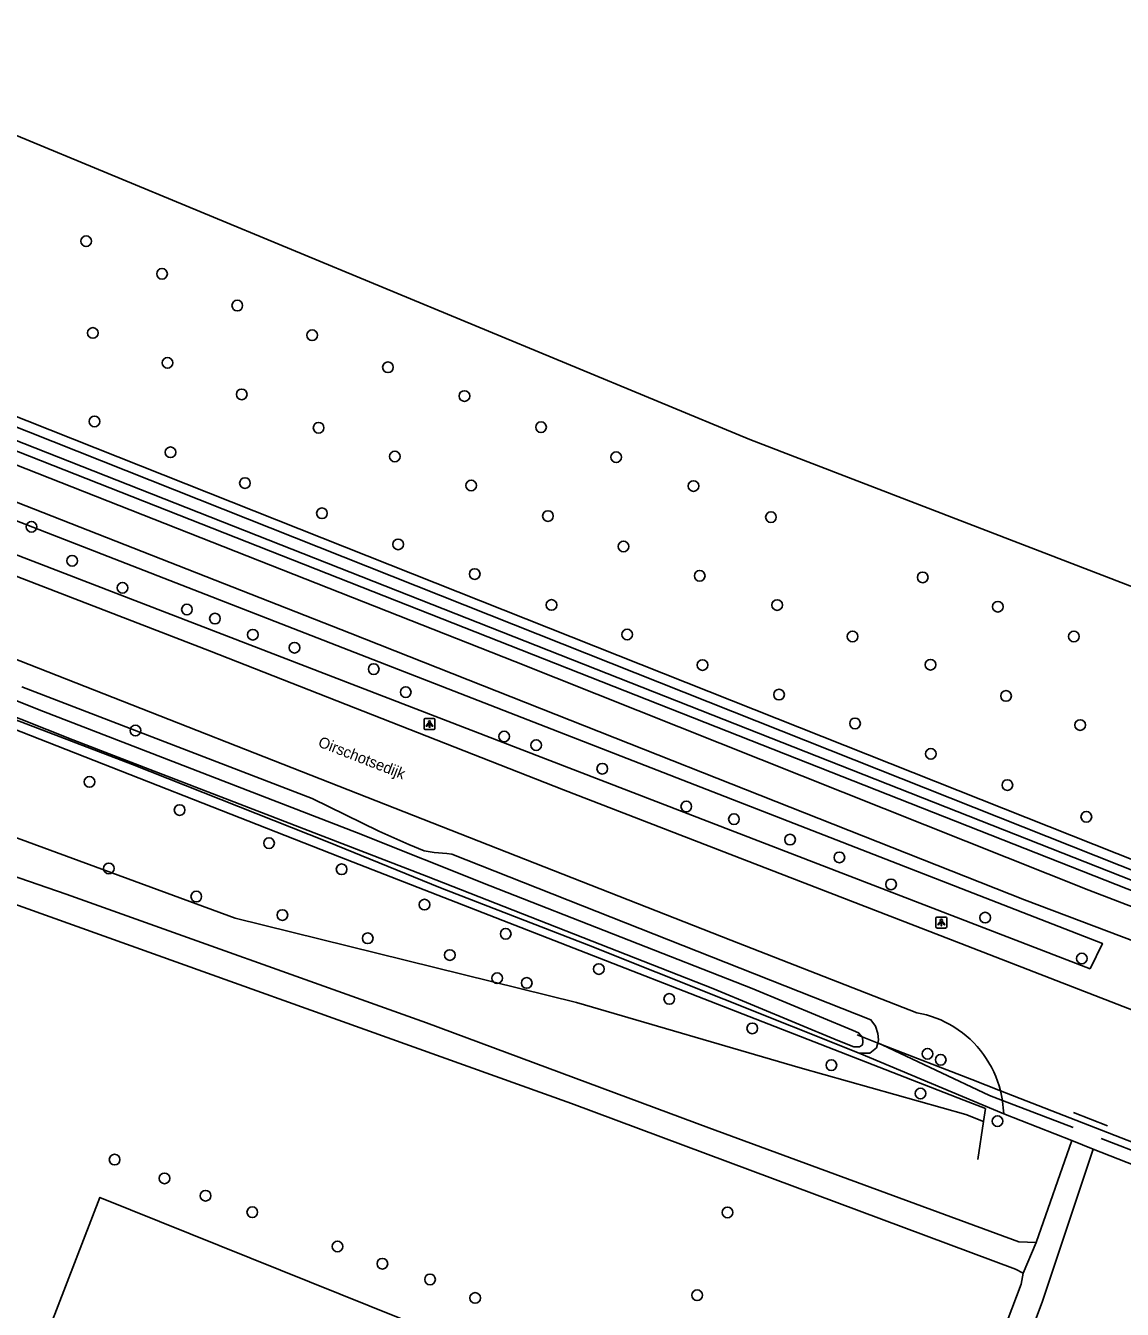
# Model space of a CAD drawing. Extents: x 155209 to 156823, y 385356 to 388482.
# Drawn here: x 155552.9 to 155653.4, y 386737.4 to 386855.1 of the extents above; entities that cross this region are included whole.
import ezdxf

# ---------------------------------------------------------------- set-up
doc = ezdxf.new("R2010")
doc.units = 0
for name, color, linetype in [('IMGEO_Berm_groen', 7, 'Continuous'), ('IMGEO_Boom', 7, 'Continuous'), ('IMGEO_Duiker', 7, 'Continuous'), ('IMGEO_Fietspad_gesloten', 7, 'Continuous'), ('IMGEO_Gemengd_bos', 7, 'Continuous'), ('IMGEO_Groenvoorziening', 7, 'Continuous'), ('IMGEO_Hek', 7, 'Continuous'), ('IMGEO_Lichtpunt', 7, 'Continuous'), ('IMGEO_Openbare_ruimte_label', 7, 'Continuous'), ('IMGEO_Rijbaan_lokaal_gesloten', 7, 'Continuous'), ('IMGEO_Rijbaan_lokaal_halfverhard', 7, 'Continuous'), ('IMGEO_Waterloop', 7, 'Continuous')]:
    doc.layers.add(name, color=color, linetype=linetype)

msp = doc.modelspace()

# ---------------------------------------------------------------- linework, layer by layer
at = {"layer": 'IMGEO_Berm_groen'}
for points in [[(155482.51, 386846.03), (155487.29, 386843.95), (155500, 386838.42), (155529.93, 386825.41), (155544.85, 386818.92), (155660.25, 386773.45)], [(155631.02, 386761.84), (155631.09, 386762.12), (155631.03, 386762.7), (155630.81, 386763.38), (155630.4, 386763.97), (155591.96, 386779.14), (155591.53, 386779.21), (155590.36, 386779.31), (155589.43, 386779.44), (155588.04, 386780.02), (155585.27, 386781.26), (155579.17, 386784.25), (155552.56, 386794.49)], [(155642.45, 386756.57), (155641.27, 386757.02), (155631.41, 386761.68), (155631.02, 386761.84)]]:
    msp.add_lwpolyline(points, dxfattribs=at)
at = {"layer": 'IMGEO_Boom'}
for centre in [(155558.45, 386835.33), (155565.41, 386832.34), (155572.31, 386829.43), (155559.07, 386826.92), (155579.17, 386826.71), (155565.91, 386824.18), (155586.12, 386823.77), (155572.71, 386821.29), (155593.13, 386821.14), (155559.22, 386818.81), (155579.76, 386818.23), (155600.15, 386818.28), (155566.19, 386815.98), (155586.75, 386815.6), (155607.04, 386815.53), (155573.01, 386813.16), (155593.75, 386812.94), (155614.13, 386812.89), (155580.07, 386810.39), (155600.79, 386810.14), (155621.23, 386810.04), (155553.44, 386809.15), (155587.05, 386807.54), (155607.71, 386807.35), (155557.17, 386806.04), (155594.07, 386804.82), (155614.7, 386804.66), (155635.14, 386804.52), (155561.78, 386803.56), (155567.69, 386801.57), (155601.11, 386801.99), (155621.8, 386801.98), (155642.03, 386801.83), (155570.26, 386800.74), (155573.73, 386799.26), (155608.05, 386799.28), (155628.71, 386799.1), (155649, 386799.1), (155577.55, 386798.07), (155584.81, 386796.11), (155614.95, 386796.48), (155635.85, 386796.51), (155587.75, 386794), (155621.97, 386793.77), (155642.78, 386793.65), (155628.94, 386791.13), (155649.58, 386790.98), (155562.97, 386790.48), (155596.77, 386789.93), (155599.71, 386789.14), (155635.89, 386788.34), (155605.77, 386786.98), (155558.76, 386785.77), (155642.9, 386785.48), (155567.02, 386783.19), (155613.47, 386783.52), (155650.14, 386782.57), (155617.84, 386782.36), (155575.22, 386780.16), (155622.98, 386780.48), (155560.53, 386777.84), (155581.87, 386777.76), (155627.5, 386778.85), (155632.24, 386776.38), (155568.55, 386775.26), (155589.47, 386774.52), (155576.44, 386773.57), (155640.87, 386773.33), (155596.91, 386771.85), (155584.26, 386771.44), (155591.79, 386769.9), (155649.73, 386769.58), (155605.45, 386768.62), (155596.13, 386767.78), (155598.84, 386767.34), (155611.91, 386765.88), (155619.52, 386763.18), (155635.58, 386760.85), (155636.79, 386760.3), (155626.77, 386759.81), (155634.94, 386757.21), (155642, 386754.68), (155561.06, 386751.15), (155565.64, 386749.43), (155569.4, 386747.84), (155573.68, 386746.33), (155617.25, 386746.31), (155581.49, 386743.19), (155585.61, 386741.61), (155589.98, 386740.17), (155594.11, 386738.47), (155614.46, 386738.72)]:
    msp.add_circle(centre, 0.489, dxfattribs=at)
at = {"layer": 'IMGEO_Duiker'}
msp.add_lwpolyline([(155666.33, 386748.06), (155664.02, 386748.99), (155661.42, 386750), (155656.8, 386751.8), (155642.28, 386757.45), (155639.65, 386758.48), (155631.41, 386761.68), (155629.14, 386762.58)], dxfattribs=at)
at = {"layer": 'IMGEO_Fietspad_gesloten'}
for points in [[(155664.94, 386770.25), (155650.37, 386775.84), (155597.75, 386796.8), (155542.24, 386818.67), (155529.41, 386824.07), (155500, 386836.47), (155486.55, 386842.14), (155476.96, 386846.12)], [(155657.25, 386770.12), (155644.46, 386774.96), (155582.64, 386799.4), (155542.08, 386815.32), (155528.28, 386821.17), (155500, 386833.17), (155494.87, 386835.35), (155485.35, 386839.2), (155476.04, 386842.96), (155472.84, 386844.21)]]:
    msp.add_lwpolyline(points, dxfattribs=at)
at = {"layer": 'IMGEO_Gemengd_bos'}
for points in [[(155501.63, 386865.96), (155619.3, 386817.16), (155711.43, 386781.69)], [(155484.42, 386847.58), (155500, 386841.03), (155546.79, 386821.35), (155661.24, 386775.91)], [(155609.34, 386713.39), (155610.76, 386716.71), (155614.71, 386725.57), (155559.71, 386747.69), (155554.38, 386733.89), (155557.42, 386732.74)]]:
    msp.add_lwpolyline(points, dxfattribs=at)
at = {"layer": 'IMGEO_Groenvoorziening'}
for points in [[(155463.65, 386822.31), (155477.84, 386817.46), (155484.11, 386815.5), (155520.82, 386802.04), (155551.64, 386790.69), (155581.69, 386778.9), (155638.9, 386756.61), (155640.89, 386755.83), (155640.71, 386754.64), (155639.1, 386755.3), (155623.92, 386759.56), (155603.41, 386765.55), (155572.12, 386773.29), (155551.59, 386780.84), (155540.07, 386789.5), (155532.09, 386790.73), (155519.31, 386789.64)], [(155464.51, 386822.78), (155475.66, 386819.02), (155489.2, 386815.03), (155500, 386810.91), (155511.9, 386806.37), (155519.03, 386804.42), (155529.27, 386800.13), (155562.69, 386787.37), (155580.53, 386780.3), (155590.94, 386776.05), (155604.5, 386770.82), (155629.33, 386760.9)], [(155629.33, 386760.9), (155630.3, 386760.91), (155630.91, 386761.41), (155631.02, 386761.84)], [(155642.58, 386755.34), (155629.33, 386760.9)]]:
    msp.add_lwpolyline(points, dxfattribs=at)
at = {"layer": 'IMGEO_Hek'}
for points in [[(155581.69, 386778.9), (155551.64, 386790.69), (155520.82, 386802.04)], [(155581.69, 386778.9), (155638.9, 386756.61)], [(155641.27, 386757.02), (155642.45, 386756.57)], [(155638.9, 386756.61), (155640.89, 386755.83)], [(155642.45, 386756.57), (155648.93, 386754.08)], [(155640.89, 386755.83), (155640.71, 386754.64)], [(155648.97, 386755.46), (155652.09, 386754.26)], [(155640.71, 386754.64), (155640.18, 386751.15)], [(155651.51, 386753.09), (155655.94, 386751.39)]]:
    msp.add_lwpolyline(points, dxfattribs=at)
at = {"layer": 'IMGEO_Lichtpunt'}
for p, q in [((155589.43, 386791.49), (155589.43, 386790.68)), ((155589.43, 386791.49), (155589.43, 386790.68)), ((155590.33, 386791.58), (155589.53, 386791.58)), ((155590.33, 386791.58), (155589.53, 386791.58)), ((155590.43, 386790.68), (155590.43, 386791.49)), ((155590.43, 386790.68), (155590.43, 386791.49)), ((155589.53, 386790.58), (155590.33, 386790.58)), ((155589.53, 386790.58), (155590.33, 386790.58)), ((155636.35, 386773.29), (155636.35, 386772.48)), ((155636.35, 386773.29), (155636.35, 386772.48)), ((155637.25, 386773.38), (155636.45, 386773.38)), ((155637.25, 386773.38), (155636.45, 386773.38)), ((155636.45, 386772.38), (155637.25, 386772.38)), ((155636.45, 386772.38), (155637.25, 386772.38)), ((155637.35, 386772.48), (155637.35, 386773.29)), ((155637.35, 386772.48), (155637.35, 386773.29))]:
    msp.add_line(p, q, dxfattribs=at)
for points in [[(155589.81, 386791.15), (155589.84, 386791.12), (155589.66, 386790.86), (155589.62, 386790.89), (155589.81, 386791.15)], [(155590.02, 386791.12), (155590.06, 386791.15), (155590.24, 386790.89), (155590.2, 386790.86), (155590.02, 386791.12)], [(155589.91, 386791.1), (155589.96, 386791.1), (155589.96, 386790.78), (155589.91, 386790.78), (155589.91, 386791.1)], [(155636.73, 386772.95), (155636.76, 386772.92), (155636.58, 386772.66), (155636.54, 386772.69), (155636.73, 386772.95)], [(155636.83, 386772.9), (155636.87, 386772.9), (155636.87, 386772.58), (155636.83, 386772.58), (155636.83, 386772.9)], [(155636.94, 386772.92), (155636.98, 386772.95), (155637.16, 386772.69), (155637.12, 386772.66), (155636.94, 386772.92)]]:
    msp.add_lwpolyline(points, dxfattribs=at)
for centre in [(155589.93, 386791.28), (155636.85, 386773.08)]:
    msp.add_circle(centre, 0.0994, dxfattribs=at)
for centre, start, end in [((155589.53, 386791.49), 90, 180), ((155589.53, 386791.49), 90, 180), ((155590.33, 386791.49), 0, 90), ((155590.33, 386791.49), 0, 90), ((155589.53, 386790.68), 180, 270), ((155589.53, 386790.68), 180, 270), ((155590.33, 386790.68), 270, 0), ((155590.33, 386790.68), 270, 360), ((155636.45, 386773.29), 90, 180), ((155636.45, 386773.29), 90, 180), ((155636.45, 386772.48), 180, 270), ((155636.45, 386772.48), 180, 270), ((155637.25, 386773.29), 0, 90), ((155637.25, 386773.29), 0, 90), ((155637.25, 386772.48), 270, 0), ((155637.25, 386772.48), 270, 360)]:
    msp.add_arc(centre, 0.0946, start, end, dxfattribs=at)
at = {"layer": 'IMGEO_Rijbaan_lokaal_gesloten'}
for points in [[(155471.87, 386835.61), (155498.72, 386825.29), (155500, 386824.8), (155508.89, 386821.38), (155525.8, 386814.81), (155543.69, 386807.85), (155569.76, 386797.77), (155602.21, 386785.04), (155637.7, 386771.32), (155656.5, 386764.02)], [(155464.21, 386831.23), (155478.14, 386825.82), (155496.81, 386818.68), (155500, 386817.43), (155523.26, 386808.3), (155617.56, 386771.28), (155634.6, 386764.62)], [(155642.28, 386757.45), (155642.3, 386757.34), (155642.45, 386756.57)], [(155642.58, 386755.34), (155642.55, 386755.63), (155642.46, 386756.49), (155642.45, 386756.57)], [(155648.8, 386752.89), (155642.58, 386755.34)], [(155648.8, 386752.89), (155650.78, 386752.11)], [(155654.58, 386750.61), (155650.78, 386752.11)]]:
    msp.add_lwpolyline(points, dxfattribs=at)
for centre, radius, start, end in [((155632.9, 386755.1), 9.67, 58.1118, 79.8493), ((155632.9, 386755.11), 9.66, 14.0116, 58.0942)]:
    msp.add_arc(centre, radius, start, end, dxfattribs=at)
at = {"layer": 'IMGEO_Rijbaan_lokaal_halfverhard'}
for points in [[(155645.55, 386743.55), (155643.96, 386743.63), (155615.52, 386754.06), (155589.64, 386763.7), (155556.62, 386775.48), (155548.01, 386778.45)], [(155545.77, 386776.43), (155548.13, 386775.92), (155602.96, 386756.31), (155643.64, 386741.11), (155644.34, 386740.74)], [(155645.55, 386743.55), (155648.8, 386752.89)], [(155650.78, 386752.11), (155646.13, 386738.19), (155636.4, 386712.24), (155627.03, 386686.65), (155606.99, 386633), (155605.46, 386628.53), (155594.88, 386600.99), (155587.3, 386580.96)], [(155644.34, 386740.74), (155645.55, 386743.55)], [(155584.86, 386581.8), (155593.26, 386603.28), (155604.83, 386634.04), (155624.86, 386687.72), (155634.14, 386713.25), (155644.18, 386739.73), (155644.34, 386740.74)]]:
    msp.add_lwpolyline(points, dxfattribs=at)
at = {"layer": 'IMGEO_Waterloop'}
for points in [[(155482.06, 386847.19), (155487.65, 386844.78), (155500.36, 386839.25), (155530.29, 386826.24), (155545.2, 386819.76), (155659.68, 386774.64), (155660.33, 386774.45), (155660.55, 386774.4)], [(155660.76, 386775.11), (155659.93, 386775.45), (155546.44, 386820.52), (155499.65, 386840.19), (155484.06, 386846.75)], [(155475.22, 386841.64), (155484.65, 386837.49), (155500, 386830.78), (155511.58, 386825.73), (155520.65, 386822.29), (155527.61, 386819.45), (155541.14, 386813.94), (155651.62, 386770.97), (155650.5, 386768.64)], [(155650.5, 386768.64), (155526.43, 386816.44), (155523.28, 386817.66), (155500, 386827.48), (155499.42, 386827.72), (155473.59, 386839.43)], [(155547.51, 386793.47), (155557.23, 386789.62), (155574.54, 386782.97), (155589.65, 386777.14), (155615.9, 386766.82), (155627.35, 386762.06), (155628.82, 386761.48), (155629.34, 386761.48), (155629.61, 386761.66), (155629.66, 386761.94), (155629.63, 386762.34), (155629.26, 386762.78), (155628.76, 386763), (155619.52, 386766.83), (155595.49, 386776.25), (155583.24, 386781.13), (155554.54, 386792.23), (155533.91, 386800.4)]]:
    msp.add_lwpolyline(points, dxfattribs=at)

# ---------------------------------------------------------------- texts
at = {"layer": 'IMGEO_Openbare_ruimte_label'}
msp.add_text('Oirschotsedijk', height=1, rotation=338.7198, dxfattribs=at).set_placement((155579.64, 386789.04))

doc.saveas('drawing.dxf')
